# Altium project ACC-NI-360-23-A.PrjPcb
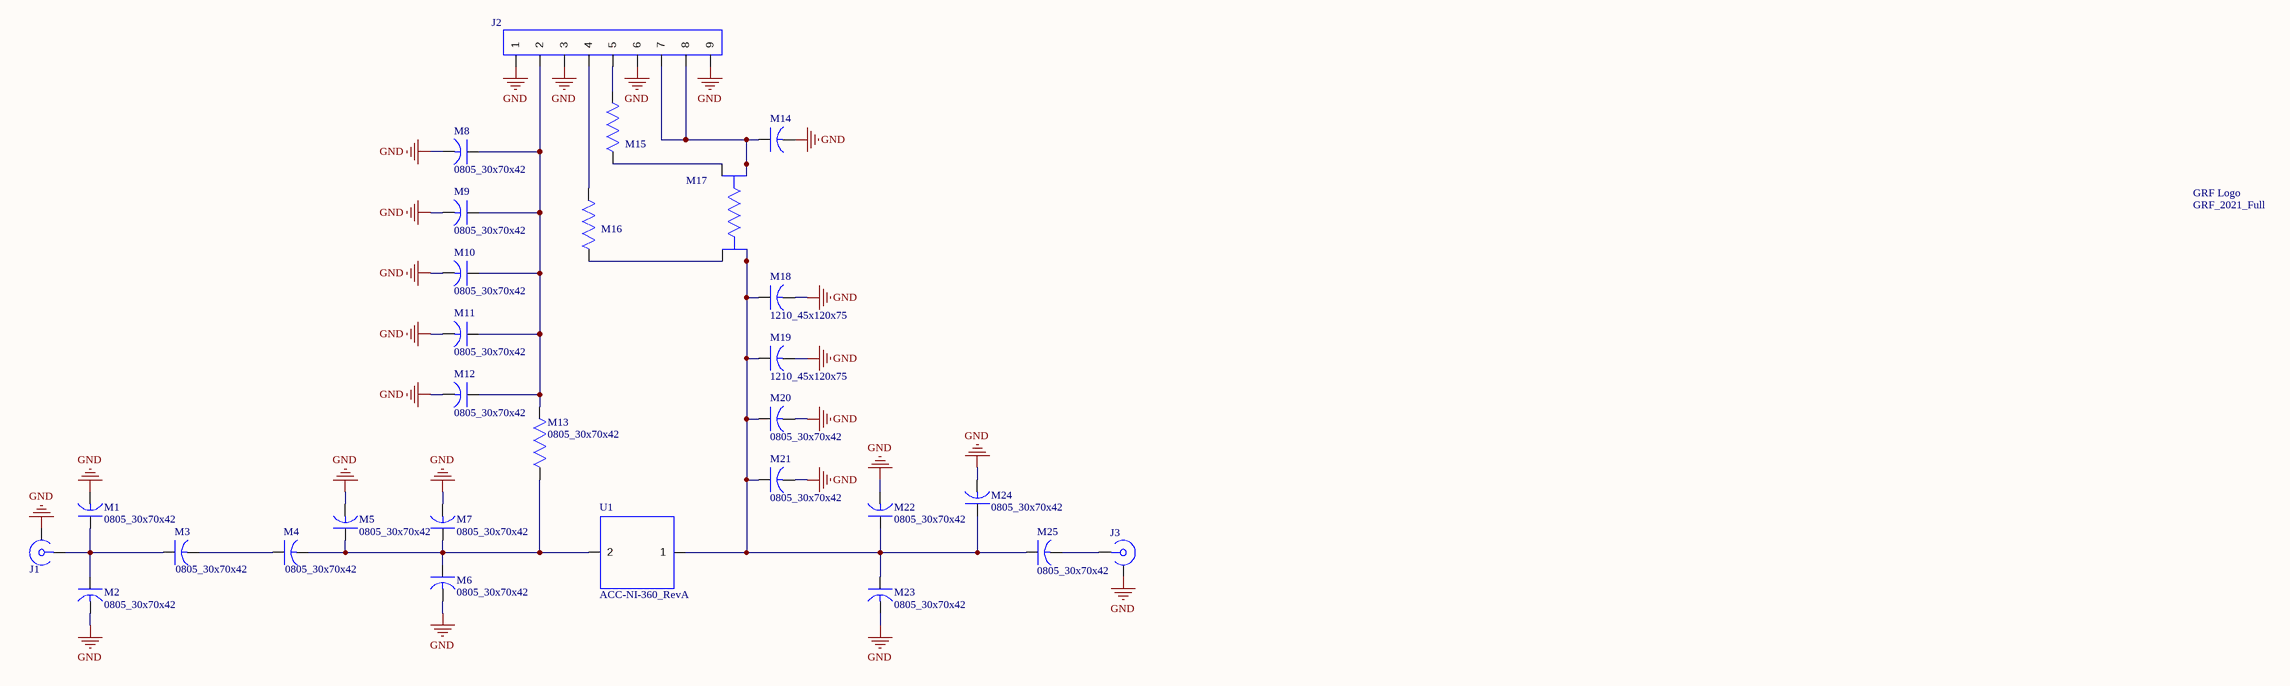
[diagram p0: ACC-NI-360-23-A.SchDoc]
Description: Layout updates; Modified From: DFN6-15-34-A (Eagle)
1 sheet, 30 parts. Net scope: global (net labels, ports and power ports of the same name join across sheets).
Board file: ACC-NI-360-23-A.PcbDoc

## Sheet ACC-NI-360-23-A.SchDoc
size 609 x 419 mm; Revision: A; SheetNumber: 1; SheetTotal: 1

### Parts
J1  SMA Panel Mount_RevB  [SMA Panel Mount_RevB]  (value not drawn)
J2  Header_H_9-Pin_100mil  [Header_H_9-Pin_100mil]  (value not drawn)
J3  SMA Panel Mount_RevB  [SMA Panel Mount_RevB]  (value not drawn)
Logo1  GRF_2021_Full  [GRF_2021_Full]
M1  0805_30x70x42  [0805_30x70x42]
M2  0805_30x70x42  [0805_30x70x42]
M3  0805_30x70x42  [0805_30x70x42]
M4  0805_30x70x42  [0805_30x70x42]
M5  0805_30x70x42  [0805_30x70x42]
M6  0805_30x70x42  [0805_30x70x42]
M7  0805_30x70x42  [0805_30x70x42]
M8  0805_30x70x42  [0805_30x70x42]
M9  0805_30x70x42  [0805_30x70x42]
M10  0805_30x70x42  [0805_30x70x42]
M11  0805_30x70x42  [0805_30x70x42]
M12  0805_30x70x42  [0805_30x70x42]
M13  0805_30x70x42  [0805_30x70x42]
M14  Comment  [Panasonic_K-Size]  (value not drawn)
M15  0402_26x26x20  [0402_26x26x20]  (value not drawn)
M16  0402_26x26x20  [0402_26x26x20]  (value not drawn)
M17  Ohmite_LVK12  [Ohmite_LVK12]  (value not drawn)
M18  1210_45x120x75  [1210_45x120x75]
M19  1210_45x120x75  [1210_45x120x75]
M20  0805_30x70x42  [0805_30x70x42]
M21  0805_30x70x42  [0805_30x70x42]
M22  0805_30x70x42  [0805_30x70x42]
M23  0805_30x70x42  [0805_30x70x42]
M24  0805_30x70x42  [0805_30x70x42]
M25  0805_30x70x42  [0805_30x70x42]
U1  ACC-NI-360_RevA  [ACC-NI-360_RevA]

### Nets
GND: J1.2 J2.1 J2.3 J2.6 J2.9 J3.2 M1.1 M2.1 M5.1 M6.1 M7.1 M8.1 M9.1 M10.1 M11.1 M12.1 M14.1 M18.2 M19.2 M20.1 M21.1 M22.1 M23.1 M24.1
NetJ1_1: J1.1 M1.2 M2.2 M3.2
NetJ2_2: J2.2 M8.2 M9.2 M10.2 M11.2 M12.2 M13.2
NetJ2_4: J2.4 M16.2
NetJ2_5: J2.5 M15.2
NetJ2_7: J2.7 J2.8 M14.2 M17.4
NetJ3_1: J3.1 M25.1
NetM3_1: M3.1 M4.2
NetM4_1: M4.1 M5.2 M6.2 M7.2 M13.1 U1.2
NetM15_1: M15.1 M17.1
NetM16_1: M16.1 M17.2
NetM17_3: M17.3 M18.1 M19.1 M20.2 M21.2 M22.2 M23.2 M24.2 M25.2 U1.1

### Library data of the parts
J1 J3 = RF_Conn
J2 = Header_9-Pin: Header 9-Pin
Logo1 = GRF_Logo: =CurrentFootprint
M1-M12 M14 M18-M25 = Capacitor
M13 M15 M16 = Resistor
M17 = Resistor_Ohmite_Current_Sense
U1 = ACC-NI-360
